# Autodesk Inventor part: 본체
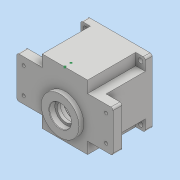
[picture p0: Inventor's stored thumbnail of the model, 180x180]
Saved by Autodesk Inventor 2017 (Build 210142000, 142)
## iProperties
Part Number: 본체
Material: 일반
Document SubType Name: Modeling
Designer: user
Density: 1 g/cm^3
Appearance: 기본값
Author: user
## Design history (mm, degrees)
sketch "스케치1"
  geometry: L1 (0, -94)-(-33, -94); L2 (-33, -94)-(-33, -77); L3 (-33, -77)-(-70, -77); L4 (-70, -77)-(-70, -17); L5 (-70, -17)-(-33, -17); L6 (-33, -17)-(-33, 0); L7 (-33, 0)-(0, 0); L8 (0, -94)-(0, 0); L9 (0, -94)-(33, -94); L10 (33, -94)-(33, -77); L11 (33, -77)-(70, -77); L12 (70, -77)-(70, -17); L13 (70, -17)-(33, -17); L14 (33, -17)-(33, 0); L15 (33, 0)-(0, 0)
  constraints: 30 end point, 6 perpendicular, 6 symmetric about line, 2 horizontal
  dimensions: "d0" = 94 distance between parallel lines of L7 L1; "d1" = 33 distance from line of L7.end L2; "d2" = 70 distance from line of L7.end L4; "d3" = 33 distance from line of L7.end L6; "d4" = 60 distance between parallel lines of L5 L3; "d5" = 17 distance between parallel lines of L3 L1
extrude "돌출1" new body sketch "스케치1" distance "d6" = 13; taper "d7" = 0 deg
sketch "스케치3"
  geometry: L1 (-33, 0)-(33, 0) reference; L2 (33, 94)-(-33, 94) reference; L3 (-33, 94)-(33, 94); L4 (33, 77)-(33, 94) reference; L5 (33, 94)-(33, 77); L6 (33, 77)-(47, 77); L7 (70, 77)-(33, 77) reference; L8 (47, 77)-(47, 17); L9 (33, 17)-(70, 17) reference; L10 (33, 17)-(33, 0); L11 (33, 0)-(0, 0); L12 (-33, 17)-(-33, 0) reference; L13 (-33, 0)-(-33, 17); L14 (-33, 17)-(-47, 17); L15 (-70, 17)-(-33, 17) reference; L16 (-33, 77)-(-70, 77) reference; L17 (-47, 77)-(-33, 77); L18 (-33, 94)-(-33, 77) reference; L19 (-33, 77)-(-33, 94); L20 (-47, 77)-(-47, 17); L21 (0, 0)-(-33, 0); L22 (47, 17)-(33, 17)
  constraints: 26 end point, 4 collinear, 3 perpendicular, 3 point on line, 3 vertical, 1 horizontal
  dimensions: "d13" = 47 horizontal distance of L6.end L11.end; "d15" = 47 distance from line of L20 L11.end
extrude "돌출3" join sketch "스케치3" distance "d16" = 57; taper "d17" = 0 deg
sketch "스케치4"
  geometry: L1 (-47, 94)-(47, 94); L2 (47, 94)-(47, 0); L3 (47, 0)-(-47, 0); L4 (-47, 0)-(-47, 94); L5 (33, 94)-(-33, 94) reference; 2 further points
  constraints: 8 end point, 2 midpoint, 2 parallel, 1 horizontal, 1 perpendicular
  dimensions: "d18" = 94 distance of L2.end L3.end; "d19" = 94 distance of L1.end L2.end; "d20" = 47 distance from line of L4 point (0, 0)
extrude "돌출4" join sketch "스케치4" distance "d21" = 10; taper "d22" = 0 deg
sketch "스케치6"
  geometry: L1 (47, 94)-(-47, 94) reference; L2 (-47, 94)-(-47, 0) reference; C1 r 3.5 at (-40, 87); 1 further point
  constraints: 1 centre point
  dimensions: "d27" = 7 diameter of C1; "d28" = 7 distance from line of L1 C1.centre; "d29" = 7 distance from line of L2 C1.centre
extrude "돌출5" cut sketch "스케치6" distance "d30" = 30; taper "d31" = 0 deg
sketch "스케치8"
  geometry: 1 further point
sketch "스케치11"
  geometry: L1 (47, 94)-(-47, 94) reference; L2 (-47, 0)-(47, 0) reference; C1 r 43 at (0, 47); 2 further points
  constraints: 1 centre point, 1 midpoint, 1 vertical alignment
  dimensions: "d51" = 86 diameter of C1; "d52" = 47 distance from line of L1 C1.centre
extrude "돌출9" cut sketch "스케치11" distance "d53" = 9; taper "d54" = 0 deg
sketch "스케치12"
  geometry: C1 r 40 at (0, 0); C2 r 43 at (0, 0) reference; 1 further point
  constraints: 1 centre point, 1 concentric
  dimensions: "d55" = 80 diameter of C1
extrude "돌출10" cut sketch "스케치12" distance "d56" = 62; taper "d57" = 0 deg
sketch "스케치13"
  geometry: 1 further point
sketch "스케치14"
  geometry: C1 r 21 at (0, 11); C2 r 15 at (0, -20); C3 r 40 at (0, 0) reference; 1 further point
  constraints: 2 centre point, 2 vertical alignment
  dimensions: "d58" = 42 diameter of C1; "d59" = 30 diameter of C2; "d60" = 11 distance of C3.centre C1.centre; "d61" = 20 distance of C2.centre C3.centre
extrude "돌출11" join sketch "스케치14" distance "d62" = 7; taper "d63" = 0 deg
sketch "스케치15"
  geometry: L1 (-33, 0)-(33, 0) reference; L2 (-33, -17)-(-33, 0) reference; L3 (-70, -17)-(-33, -17) reference; L4 (-70, -77)-(-70, -17) reference; L5 (-33, -77)-(-70, -77) reference; L6 (-33, -94)-(-33, -77) reference; L7 (33, -94)-(-33, -94) reference; L8 (33, -77)-(33, -94) reference; L9 (70, -77)-(33, -77) reference; L10 (70, -17)-(70, -77) reference; L11 (33, -17)-(70, -17) reference; L12 (33, 0)-(33, -17) reference; C1 r 16 at (0, -58); C2 r 40 at (0, -47) reference; 1 further point
  constraints: 1 centre point, 1 vertical alignment
  dimensions: "d64" = 32 diameter of C1; "d65" = 11 distance of C2.centre C1.centre
extrude "돌출12" cut sketch "스케치15" distance "d66" = 1.3; taper "d67" = 0 deg
sketch "스케치16"
  geometry: C1 r 12.5 at (0, 0); C2 r 16 at (0, 0) reference; 1 further point
  constraints: 1 centre point, 1 concentric
  dimensions: "d68" = 25 diameter of C1
extrude "돌출13" cut sketch "스케치16" distance "d69" = 4.7; taper "d70" = 0 deg
sketch "스케치17"
  geometry: L1 (47, -19)-(47, 41) reference; C1 r 17.5 at (0, 0); A1 r 21 centre (0, 0) between (-8.978, 18.984) and (8.978, 18.984) reference; 1 further point
  constraints: 1 centre point, 1 concentric
  dimensions: "d71" = 35 diameter of C1
extrude "돌출14" cut sketch "스케치17" distance "d72" = 10; taper "d73" = 0 deg
sketch "스케치18"
  geometry: C1 r 11 at (0, -20); A1 r 15 centre (0, -20) between (-8.978, -7.984) and (8.978, -7.984) reference; 1 further point
  constraints: 1 centre point, 1 concentric
  dimensions: "d74" = 22 diameter of C1
extrude "돌출15" cut sketch "스케치18" distance "d75" = 7; taper "d76" = 0 deg
sketch "스케치19"
  geometry: C1 r 9.5 at (0, 0); C2 r 11 at (0, 0) reference; 1 further point
  constraints: 1 centre point, 1 concentric
  dimensions: "d77" = 19 diameter of C1
extrude "돌출16" cut sketch "스케치19" distance "d78" = 3; taper "d79" = 0 deg
sketch "스케치20"
  geometry: L1 (-14, 80)-(80, 80) reference; L2 (0, 0)-(66, 0) reference; 3 further points
  constraints: 1 midpoint, 1 vertical alignment, 1 other
  dimensions: "d81" = 40 distance from line of L1 point (33, 40)
feature "엠보싱2" sketch "스케치20" dims "d0" = 94, "d1" = 33, "d2" = 70, "d3" = 33, "d4" = 60, "d5" = 17, "d82" = 0.5, "d83" = 0
sketch "스케치21"
  geometry: C1 r 27.5 at (0, -58); C2 r 16 at (0, -58) reference; 1 further point
  constraints: 1 centre point, 1 concentric
  dimensions: "d84" = 55 diameter of C1
extrude "돌출17" join sketch "스케치21" distance "d85" = 7; taper "d86" = 0 deg
sketch "스케치22"
  geometry: L1 (-47, 0)-(47, 0) reference; L2 (70, 17)-(70, 77) reference; L3 (47, 17)-(70, 17) reference; 2 further points
  dimensions: "d88" = 10 distance from line of L2 point (60, 28); "d89" = 11 distance from line of point (60, 28) L3
hole "구멍1" sketch "스케치22" at (60, 28) diameter "d90" = 4.5; stored, may be unused: countersink angle "d94" = 90 deg, drill point angle "d96" = 0 deg; dims "d91" = 6, "d92" = 10, "d93" = 5, "d95" = 8
sketch "스케치24"
  geometry: A1 r 40 centre (0, 0) between (39.279, -7.559) and (39.279, 7.559) reference; A2 r 4 centre (36, 0) between (36.19, 3.995) and (36.19, -3.995); A3 r 3 centre (36.333, -6.992) between (39.279, -7.559) and (36.19, -3.995); A4 r 3 centre (36.333, 6.992) between (36.19, 3.995) and (39.279, 7.559); 1 further point
  constraints: 8 point on circle, 4 tangent, 3 centre point, 1 horizontal alignment
  dimensions: "d101" = 8 diameter of A2; "d102" = 36 distance of A2.centre A1.centre; "d103" = 3 radius of A3; "d104" = 3 radius of A4
extrude "돌출18" join sketch "스케치24" stored distance "d105" = 7; taper "d106" = 0 deg
sketch "스케치25"
  geometry: C1 r 43 at (0, 0) reference; A1 r 40 centre (0, 0) between (39.279, 7.559) and (39.279, -7.559) reference; A2 r 3 centre (36.333, 6.992) between (36.19, 3.995) and (39.279, 7.559) reference; A3 r 4 centre (36, 0) between (36.19, 3.995) and (36.19, -3.995) reference; A4 r 3 centre (36.333, -6.992) between (39.279, -7.559) and (36.19, -3.995) reference; 2 further points
  constraints: 1 coincident
hole "구멍2" sketch "스케치25" at (36, 0) diameter "d107" = 3.242; stored, may be unused: countersink angle "d111" = 82 deg, drill point angle "d113" = 118 deg; dims "d108" = 7, "d109" = 3.023, "d110" = 5, "d112" = 9
fillet "모깎기1" dims "d120" = 3
chamfer "모따기1" distance "d121" = 0.8; stored, may be unused: second distance "d122" = 2, angle "d123" = 30 deg
chamfer "모따기2" distance "d124" = 1; stored, may be unused: second distance "d125" = 2, angle "d126" = 30 deg
fillet "모깎기2" dims "d127" = 3
fillet "모깎기3" dims "d128" = 3
node "솔리드1"
pattern_linear "직사각형 패턴1" dims "d34" = 80, "d37" = 80
mirror "미러1"
pattern_linear "직사각형 패턴2" dims "d116" = 120, "d119" = 38
node "투영된 루프3"
node "투영된 루프4"
node "투영된 루프5"
